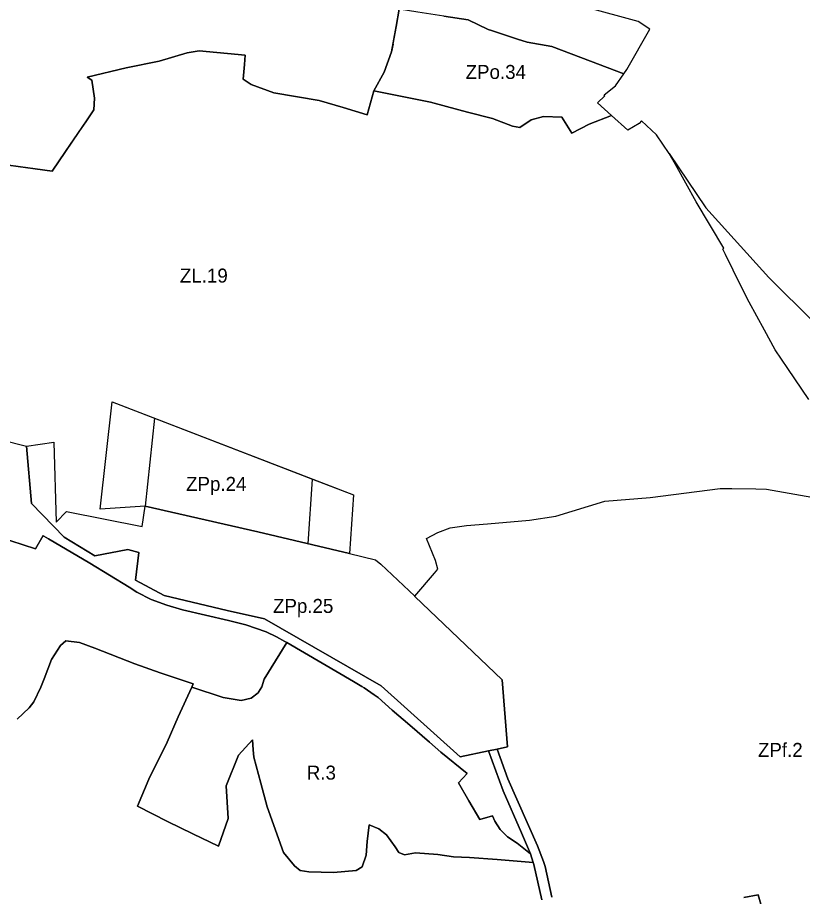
# Model space of a CAD drawing. Extents: x 7418114 to 7422197, y 5546299 to 5548348.
# Drawn here: x 7420219 to 7420780, y 5547025 to 5547653 of the extents above; entities that cross this region are included whole.
import ezdxf

# ---------------------------------------------------------------- set-up
doc = ezdxf.new("R2010")
doc.units = 0
for name, color, linetype in [('_STRZELNICA_SIKORNIK', 7, 'Continuous'), ('linie_lokalizacyjne', 7, 'Continuous'), ('linie_rozgraniczajace', 7, 'Continuous'), ('oznaczenia_przeznaczen', 7, 'Continuous')]:
    doc.layers.add(name, color=color, linetype=linetype)

msp = doc.modelspace()

# ---------------------------------------------------------------- linework, layer by layer
at = {"layer": '_STRZELNICA_SIKORNIK'}
for points in [[(7420652.21, 5547612.82), (7420652.27, 5547612.9), (7420654.42, 5547615.95), (7420670.83, 5547644.61), (7420662.5, 5547650.19), (7420547.05, 5547681.81)], [(7420268.93, 5547610.56), (7420296.8, 5547617.03), (7420320.31, 5547621.91), (7420340.34, 5547627.91), (7420349.07, 5547629.24), (7420381.76, 5547626.27), (7420381.28, 5547619.41), (7420380.36, 5547609.12), (7420386.01, 5547605.16), (7420402.4, 5547599.24), (7420434.72, 5547593.82), (7420451.81, 5547588.68), (7420468.89, 5547583.55), (7420473.64, 5547600.7), (7420481.06, 5547614.09), (7420486.2, 5547628.43), (7420489.58, 5547646.57), (7420491.71, 5547659.09)], [(7420523.59, 5547654.04), (7420541.03, 5547651.29), (7420555.4, 5547644.41), (7420557.64, 5547643.69), (7420576.25, 5547637.67), (7420583.18, 5547635.43), (7420600.78, 5547632.24), (7420628.3, 5547621.84), (7420652.21, 5547612.82)], [(7420212.89, 5547547.55), (7420244.04, 5547543.38), (7420253.59, 5547557.42), (7420268.42, 5547579.26), (7420273.7, 5547587.06), (7420274.28, 5547595.54), (7420272.44, 5547608.29), (7420268.93, 5547610.56)]]:
    msp.add_lwpolyline(points, dxfattribs=at)
at = {"layer": 'linie_lokalizacyjne'}
for points in [[(7420317.16, 5547366.87), (7420310.31, 5547304.19)], [(7420426.7, 5547277.29), (7420429.9, 5547323.4)]]:
    msp.add_lwpolyline(points, dxfattribs=at)
at = {"layer": 'linie_rozgraniczajace'}
for p, q in [((7420487.25, 5547634.07), (7420487.44, 5547634.05)), ((7420349.08, 5547629.24), (7420340.34, 5547627.92)), ((7420296.8, 5547617.03), (7420268.93, 5547610.57)), ((7420481.06, 5547614.09), (7420473.64, 5547600.7)), ((7420268.93, 5547610.57), (7420272.45, 5547608.3)), ((7420272.45, 5547608.3), (7420274.28, 5547595.54)), ((7420274.28, 5547595.54), (7420273.7, 5547587.06)), ((7420514.14, 5547592.55), (7420473.64, 5547600.7)), ((7420516.88, 5547591.81), (7420514.14, 5547592.55)), ((7420572.73, 5547575.58), (7420558.46, 5547581)), ((7420578.01, 5547574.53), (7420585.96, 5547579.97)), ((7420585.96, 5547579.97), (7420578.01, 5547574.53)), ((7420585.96, 5547579.97), (7420594.82, 5547582.4)), ((7420594.82, 5547582.4), (7420585.96, 5547579.97)), ((7420594.82, 5547582.4), (7420608.02, 5547581.84)), ((7420608.02, 5547581.84), (7420594.82, 5547582.4)), ((7420572.73, 5547575.58), (7420578.01, 5547574.53)), ((7420578.01, 5547574.53), (7420572.73, 5547575.58)), ((7420724.84, 5547483.89), (7420722.99, 5547487.53)), ((7420752.51, 5547429.86), (7420741.61, 5547449.78)), ((7420317.16, 5547366.87), (7420317.16, 5547366.87)), ((7420207.92, 5547351.59), (7420225.74, 5547346.86)), ((7420225.74, 5547346.86), (7420245.12, 5547349.93)), ((7420245.12, 5547349.93), (7420246.83, 5547292.62)), ((7420729.36, 5547316.66), (7420746.49, 5547316.58)), ((7420310.32, 5547304.19), (7420278.39, 5547302.05)), ((7420308.3, 5547289.61), (7420310.32, 5547304.19)), ((7420519.46, 5547285.24), (7420528.12, 5547288.62))]:
    msp.add_line(p, q, dxfattribs=at)
for points in [[(7420652.27, 5547612.9), (7420628.3, 5547621.84), (7420600.78, 5547632.24), (7420583.18, 5547635.43), (7420576.25, 5547637.67), (7420557.64, 5547643.69), (7420555.4, 5547644.41), (7420541.03, 5547651.29), (7420523.59, 5547654.04), (7420505.16, 5547656.96), (7420491.71, 5547659.09), (7420489.58, 5547646.57), (7420487.25, 5547634.07)], [(7420487.44, 5547634.05), (7420486.2, 5547628.43), (7420481.06, 5547614.09)], [(7420340.34, 5547627.92), (7420320.31, 5547621.91), (7420296.8, 5547617.03)], [(7420381.28, 5547619.41), (7420381.76, 5547626.27), (7420349.08, 5547629.24)], [(7420473.64, 5547600.7), (7420468.89, 5547583.55), (7420451.81, 5547588.68), (7420434.72, 5547593.82), (7420402.4, 5547599.24), (7420386.01, 5547605.16), (7420380.36, 5547609.12), (7420381.28, 5547619.41)], [(7420608.02, 5547581.84), (7420614.96, 5547570.36), (7420627.42, 5547576.79), (7420643.36, 5547583.04), (7420633.32, 5547592.03), (7420638.71, 5547597.16), (7420638.07, 5547597.82), (7420646.17, 5547604.27), (7420652.27, 5547612.9)], [(7420473.64, 5547600.7), (7420514.14, 5547592.55), (7420516.88, 5547591.81)], [(7420516.88, 5547591.81), (7420540.55, 5547585.41), (7420558.46, 5547581), (7420572.73, 5547575.58)], [(7420558.46, 5547581), (7420540.55, 5547585.41), (7420516.88, 5547591.81)], [(7420273.7, 5547587.06), (7420268.42, 5547579.26), (7420263.14, 5547571.46), (7420253.59, 5547557.42), (7420244.05, 5547543.38)], [(7420643.36, 5547583.04), (7420627.42, 5547576.79), (7420614.96, 5547570.36), (7420608.02, 5547581.84)], [(7420689.1, 5547548.13), (7420684.48, 5547556.01), (7420675.51, 5547569.34), (7420664.84, 5547579.29), (7420663.1, 5547577.4), (7420655.04, 5547572.59), (7420643.36, 5547583.04)], [(7420784.27, 5547380.38), (7420769.29, 5547402.43), (7420760.2, 5547415.82), (7420752.51, 5547429.86), (7420741.61, 5547449.78), (7420735.83, 5547461.54), (7420724.84, 5547483.89), (7420722.99, 5547487.53), (7420723.71, 5547488.24), (7420703.9, 5547521.53), (7420689.1, 5547548.13), (7420684.45, 5547555.98), (7420684.48, 5547556.01), (7420710.64, 5547517.15), (7420755.7, 5547467.33), (7420788.05, 5547435.17)], [(7420244.05, 5547543.38), (7420214.57, 5547547.32), (7420212.89, 5547547.55)], [(7420722.99, 5547487.53), (7420723.71, 5547488.24), (7420703.9, 5547521.53), (7420689.1, 5547548.13)], [(7420741.61, 5547449.78), (7420735.83, 5547461.54), (7420724.84, 5547483.89)], [(7420784.27, 5547380.38), (7420769.29, 5547402.43), (7420760.2, 5547415.82), (7420752.51, 5547429.86)], [(7420278.39, 5547302.05), (7420286.75, 5547378.59), (7420317.16, 5547366.87)], [(7420317.16, 5547366.87), (7420317.16, 5547366.87)], [(7420317.16, 5547366.87), (7420429.9, 5547323.4), (7420459.19, 5547312.11)], [(7420207.92, 5547351.59), (7420225.74, 5547346.86), (7420229.2, 5547306.12), (7420252.58, 5547282.08), (7420274.56, 5547268.61), (7420298.08, 5547273.18), (7420305.96, 5547271), (7420303.54, 5547251.38), (7420324.01, 5547240.42), (7420368.96, 5547229.7), (7420395.64, 5547223.79), (7420478.88, 5547175.75), (7420535.33, 5547125.21), (7420555.56, 5547129.38), (7420565.96, 5547100.74)], [(7420600.89, 5547025.01), (7420596.12, 5547046.74), (7420594.76, 5547050.38), (7420590.56, 5547061.59), (7420569.31, 5547109.4), (7420561.68, 5547130.57), (7420569.03, 5547132.23), (7420565.27, 5547180.04), (7420502.89, 5547239.73), (7420502.86, 5547239.76), (7420516.91, 5547256.32), (7420519.37, 5547259.23), (7420517.71, 5547265.33), (7420511.31, 5547281.06), (7420519.46, 5547285.24), (7420528.12, 5547288.62), (7420539.86, 5547290.39), (7420554.89, 5547291.51), (7420584.84, 5547294.12), (7420603.64, 5547297.05), (7420638.57, 5547307.7), (7420671.04, 5547310.39), (7420721.08, 5547316.65), (7420729.36, 5547316.66), (7420746.49, 5547316.58), (7420754.04, 5547316.24), (7420790.41, 5547309.92)], [(7420671.04, 5547310.39), (7420721.08, 5547316.65), (7420729.36, 5547316.66)], [(7420746.49, 5547316.58), (7420754.04, 5547316.24), (7420790.41, 5547309.92)], [(7420459.19, 5547312.11), (7420456.29, 5547270.35), (7420474.93, 5547265.92), (7420478.6, 5547262.78), (7420502.86, 5547239.76), (7420516.91, 5547256.32), (7420519.37, 5547259.23), (7420517.71, 5547265.33)], [(7420528.12, 5547288.62), (7420539.86, 5547290.39), (7420554.89, 5547291.51), (7420584.84, 5547294.12), (7420603.64, 5547297.05), (7420638.57, 5547307.7), (7420671.04, 5547310.39)], [(7420246.83, 5547292.62), (7420254.22, 5547300.43), (7420308.3, 5547289.61)], [(7420196.74, 5547285.2), (7420232.09, 5547273.57), (7420237.49, 5547283.09), (7420237.96, 5547282.81), (7420241.38, 5547280.81), (7420270.99, 5547263.49), (7420298.96, 5547246.18), (7420304.53, 5547242.73), (7420314.78, 5547237.42), (7420325.78, 5547233.42), (7420337.02, 5547230.15), (7420370.02, 5547222.39), (7420382.36, 5547219.49), (7420396.86, 5547214.49), (7420404.1, 5547210.72), (7420410.2, 5547207.54), (7420411.55, 5547206.75), (7420395.5, 5547180.64), (7420393.74, 5547175.13), (7420391.37, 5547171.23), (7420391.02, 5547170.95), (7420386.17, 5547167.1), (7420378.97, 5547165.33), (7420366.08, 5547167.42), (7420343.72, 5547174.98), (7420343.72, 5547174.98), (7420344.58, 5547177.15), (7420321.14, 5547185.04), (7420302.92, 5547191.58), (7420274.36, 5547202.81), (7420263.56, 5547206.68), (7420253.83, 5547208.03), (7420249.86, 5547204.63), (7420243.52, 5547194.73), (7420238.31, 5547180.94), (7420236, 5547174.85), (7420230.88, 5547164.49), (7420227.67, 5547160.09), (7420219.04, 5547152.14)], [(7420565.96, 5547100.74), (7420579.08, 5547070.86), (7420585.63, 5547055.96), (7420575.95, 5547063.52), (7420569.24, 5547067.99), (7420563.82, 5547073.27), (7420560.09, 5547079.15), (7420558.43, 5547082.9), (7420549.41, 5547080.42), (7420541.61, 5547093.69), (7420534.07, 5547106.51), (7420540.27, 5547113.13), (7420521.42, 5547128.58), (7420513.5, 5547135.51), (7420499.34, 5547147.69), (7420486.74, 5547158.52), (7420476.77, 5547167.41), (7420473.88, 5547169.42), (7420466.74, 5547174.38), (7420465.21, 5547175.45), (7420459.25, 5547178.92), (7420436.76, 5547192.04), (7420411.55, 5547206.75), (7420410.2, 5547207.54), (7420404.1, 5547210.72), (7420396.86, 5547214.49), (7420382.36, 5547219.49), (7420370.02, 5547222.39), (7420337.02, 5547230.15), (7420325.78, 5547233.42), (7420314.78, 5547237.42), (7420304.53, 5547242.73), (7420298.96, 5547246.18), (7420270.99, 5547263.49), (7420241.38, 5547280.81), (7420237.96, 5547282.81), (7420237.49, 5547283.09), (7420232.09, 5547273.57), (7420196.74, 5547285.2)], [(7420517.71, 5547265.33), (7420511.31, 5547281.06), (7420519.46, 5547285.24)], [(7420219.04, 5547152.14), (7420227.67, 5547160.09), (7420230.88, 5547164.49), (7420236, 5547174.85), (7420238.31, 5547180.94), (7420243.52, 5547194.73), (7420249.86, 5547204.63), (7420253.83, 5547208.03), (7420263.56, 5547206.68), (7420274.36, 5547202.81), (7420302.92, 5547191.58), (7420321.14, 5547185.04), (7420344.58, 5547177.15), (7420343.72, 5547174.98), (7420343.72, 5547174.98), (7420333.87, 5547153.64), (7420326.05, 5547135.6), (7420312.99, 5547109.2), (7420304.91, 5547089.94), (7420326.41, 5547079.05), (7420344.46, 5547070.24), (7420362.83, 5547061.4), (7420369.75, 5547081.1), (7420368.3, 5547104.39), (7420377.02, 5547126.34), (7420387.02, 5547137.22), (7420387.58, 5547130.13), (7420388.06, 5547124.78), (7420392.91, 5547106.41), (7420397.62, 5547089.44), (7420409.3, 5547056.85), (7420417.03, 5547047.25), (7420420.98, 5547044.06), (7420427.32, 5547042.97), (7420444.82, 5547042.53), (7420461.12, 5547043.94), (7420465.34, 5547046.56), (7420468.28, 5547054.83), (7420468.86, 5547064.75), (7420470.3, 5547076.61), (7420477.23, 5547073.68), (7420482.84, 5547069.37), (7420488.93, 5547060.83), (7420491.57, 5547056.75), (7420495.69, 5547055.04), (7420503.35, 5547056.55), (7420519.28, 5547055.34), (7420530.51, 5547053.66), (7420542.1, 5547053.26), (7420561.78, 5547051.92), (7420587.47, 5547049.66), (7420587.9, 5547048.16), (7420593.71, 5547023.13)], [(7420593.71, 5547023.13), (7420587.9, 5547048.16), (7420587.47, 5547049.66), (7420585.63, 5547055.96), (7420579.08, 5547070.86), (7420565.96, 5547100.74), (7420555.56, 5547129.38), (7420561.68, 5547130.57), (7420569.31, 5547109.4), (7420590.56, 5547061.59), (7420594.76, 5547050.38), (7420596.12, 5547046.74), (7420600.89, 5547025.01)], [(7420737.94, 5547024.77), (7420748.01, 5547026.59), (7420753.27, 5547008.15)], [(7420753.27, 5547008.15), (7420748.01, 5547026.59), (7420737.94, 5547024.77)]]:
    msp.add_lwpolyline(points, dxfattribs=at)
for points in [[(7420278.39, 5547302.05), (7420286.75, 5547378.59), (7420459.19, 5547312.11), (7420456.29, 5547270.35), (7420390.81, 5547285.71), (7420310.32, 5547304.19)], [(7420225.74, 5547346.86), (7420245.12, 5547349.93), (7420246.83, 5547292.62), (7420254.22, 5547300.43), (7420308.3, 5547289.61), (7420310.32, 5547304.19), (7420390.81, 5547285.71), (7420456.29, 5547270.35), (7420474.93, 5547265.92), (7420478.6, 5547262.78), (7420502.86, 5547239.76), (7420502.89, 5547239.73), (7420565.27, 5547180.04), (7420569.03, 5547132.23), (7420561.68, 5547130.57), (7420555.56, 5547129.38), (7420535.33, 5547125.21), (7420478.88, 5547175.75), (7420395.64, 5547223.79), (7420368.96, 5547229.7), (7420324.01, 5547240.42), (7420303.54, 5547251.38), (7420305.96, 5547271), (7420298.08, 5547273.18), (7420274.56, 5547268.61), (7420252.58, 5547282.08), (7420229.2, 5547306.12)], [(7420304.91, 5547089.94), (7420312.99, 5547109.2), (7420326.05, 5547135.6), (7420333.87, 5547153.64), (7420343.72, 5547174.98), (7420366.08, 5547167.42), (7420378.97, 5547165.33), (7420386.17, 5547167.1), (7420391.02, 5547170.95), (7420391.37, 5547171.23), (7420393.74, 5547175.13), (7420395.5, 5547180.64), (7420411.55, 5547206.75), (7420436.76, 5547192.04), (7420459.25, 5547178.92), (7420465.21, 5547175.45), (7420466.74, 5547174.38), (7420473.88, 5547169.42), (7420476.77, 5547167.41), (7420486.74, 5547158.52), (7420499.34, 5547147.69), (7420513.5, 5547135.51), (7420521.42, 5547128.58), (7420540.27, 5547113.13), (7420534.07, 5547106.51), (7420541.61, 5547093.69), (7420549.41, 5547080.42), (7420558.43, 5547082.9), (7420560.09, 5547079.15), (7420563.82, 5547073.27), (7420569.24, 5547067.99), (7420575.95, 5547063.52), (7420585.63, 5547055.96), (7420587.47, 5547049.66), (7420561.78, 5547051.92), (7420542.1, 5547053.26), (7420530.51, 5547053.66), (7420519.28, 5547055.34), (7420503.35, 5547056.55), (7420495.69, 5547055.04), (7420491.57, 5547056.75), (7420488.93, 5547060.83), (7420482.84, 5547069.37), (7420477.23, 5547073.68), (7420470.3, 5547076.61), (7420468.86, 5547064.75), (7420468.28, 5547054.83), (7420465.34, 5547046.56), (7420461.12, 5547043.94), (7420444.82, 5547042.53), (7420427.32, 5547042.97), (7420420.98, 5547044.06), (7420417.03, 5547047.25), (7420409.3, 5547056.85), (7420397.62, 5547089.44), (7420392.91, 5547106.41), (7420388.06, 5547124.78), (7420387.58, 5547130.13), (7420387.02, 5547137.22), (7420377.02, 5547126.34), (7420368.3, 5547104.39), (7420369.75, 5547081.1), (7420362.83, 5547061.4), (7420344.46, 5547070.24), (7420326.41, 5547079.05)]]:
    msp.add_lwpolyline(points, close=True, dxfattribs=at)

# ---------------------------------------------------------------- texts
at = {"layer": 'oznaczenia_przeznaczen'}
for s, p in [('ZPo.34', (7420539.21, 5547609.17)), ('ZL.19', (7420335.21, 5547463.76)), ('ZPp.24', (7420339.6, 5547315.02)), ('ZPp.25', (7420401.68, 5547227.88)), ('ZPf.2', (7420747.94, 5547125.06)), ('R.3', (7420425.82, 5547108.86))]:
    msp.add_text(s, height=10, dxfattribs=at).set_placement(p)

doc.saveas('drawing.dxf')
